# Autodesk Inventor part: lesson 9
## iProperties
Author: E. MOSS
Created: 2001-08
Part Number: lesson 9
Document SubType Name: Sheet Metal
Designer: E. MOSS
Control State: 0
Master: False
Checked Out: False
PropertySet Name: Design Tracking Control
Length Units: 11272
Angle Units: 11279
Time Units: 11290
Mass Units: 11286
Shininess: 3
Angle Display Precision: 2
Document Length Units: 11272
Document Angle Units: 11286
Document Time Units: 11279
Document Mass Units: 11290
Document Length Units Precision: 3
Document Angle Units Precision: 2
Compacted: False
PropertySet Name: _Private Model Information
Density: 0.0
Volumn: 0.0
Area: 0.0
PropertySet Name: Model Information
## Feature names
1. Plate1
2. Bend1
3. Plate2
4. Bend2
5. Cut1
